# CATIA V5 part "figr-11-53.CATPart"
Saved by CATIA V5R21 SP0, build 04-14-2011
Part number: Part1
Bounding box of the stored display mesh (mm): x -70 to 82, y -90 to 90, z 0 to 80.806
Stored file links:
  D:\CATIA V5R21 E-RESOURCES\CATIA-V5R21\catia-v5r21-prt\c11-catia-v5r21-prt\c11-catia-v5r21-figr-11-53.CATPart
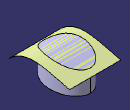
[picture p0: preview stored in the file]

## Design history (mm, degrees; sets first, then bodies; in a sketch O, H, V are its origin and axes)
Set1
  Extrude1: Element1 Sketch2, Lim1 82, Lim2 70, Direction yz-plane
Body1 (main body)
  Sketch1 on xy-plane, origin (0, 0, 0), H (1, 0, 0), V (0, 1, 0)
    ellipse A1 centre (0, 0) semi-axes 70, 50 rotation 90
    point P1 (50, 0)
    coincidence: P1 H, A1 P1
  Pad1: profile Sketch1, direction (0, 0, 1), length 84
  Split1: SplitPlane Extrude1
  Sketch2 on yz-plane, origin (0, 0, 0), H (0, 1, 0), V (0, 0, 1)
    spline S1 through (-90, 50) (-30, 80) (50, 70) (90, 60)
